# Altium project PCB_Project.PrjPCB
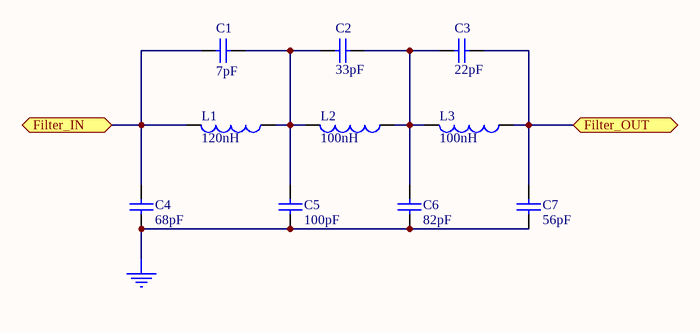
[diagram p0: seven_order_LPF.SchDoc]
4 sheets, 37 parts. Net scope: flat (ports and power ports of the same name join across sheets).
Sheets:
  Cable Modem.SchDoc
  seven_order_LPF.SchDoc
  AD9853.SchDoc
  AD8320.SchDoc

## Sheet Cable Modem.SchDoc
size B

## Sheet seven_order_LPF.SchDoc
size B

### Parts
(Parts that share a designator on the sheet are numbered #1, #2 ... from top to bottom, then left to right.)
C1#1  7pF  [C3216-1206]
C2#1  33pF  [C3216-1206]
C3#1  22pF  [C3216-1206]
C4#1  68pF  [C3216-1206]
C5#1  100pF  [C3216-1206]
C6#1  82pF  [C3216-1206]
C7#1  56pF  [C3216-1206]
L1  120nH  [C1005-0402]
L2  100nH  [C1005-0402]
L3  100nH  [C1005-0402]

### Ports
Filter_IN, Filter_OUT

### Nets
GND: C4#1.2 C5#1.2 C6#1.2 C7#1.2
NetC1#1_1: C1#1.1 C4#1.1 L1.2 ; port Filter_IN
NetC1#1_2: C1#1.2 C2#1.1 C5#1.1 L1.1 L2.2
NetC2#1_2: C2#1.2 C3#1.1 C6#1.1 L2.1 L3.2
NetC3#1_2: C3#1.2 C7#1.1 L3.1 ; port Filter_OUT

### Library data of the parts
C1#1 C2#1 C3#1 C4#1 C5#1 C6#1 C7#1 = Cap Semi: Capacitor (Semiconductor SIM Model); Manufacturer: Generic Components; Class I: Passive
L1-L3 = Inductor: Manufacturer: Generic Components; Class I: Passive

## Sheet AD9853.SchDoc
size B
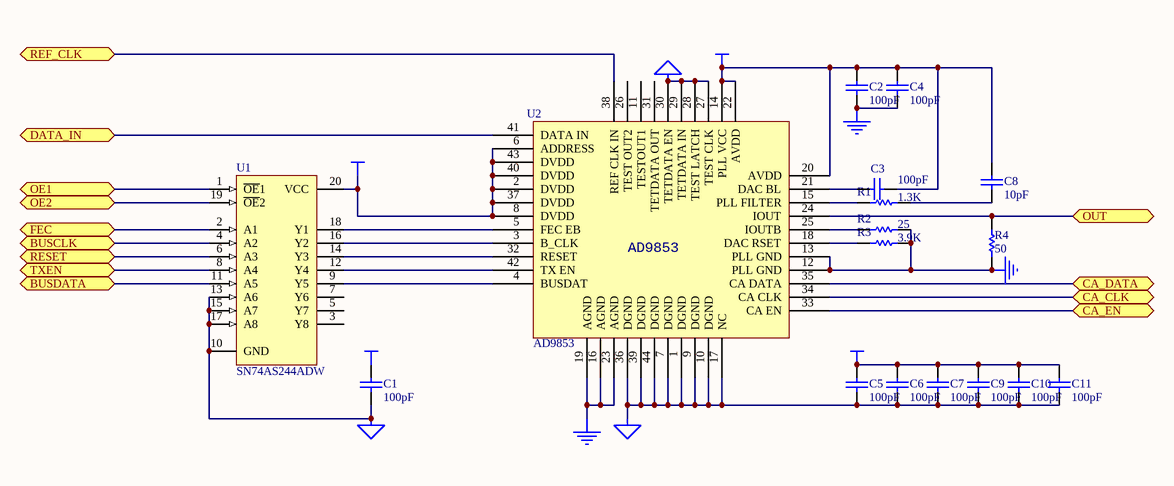
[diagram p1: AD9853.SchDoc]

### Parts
(Parts that share a designator on the sheet are numbered #1, #2 ... from top to bottom, then left to right.)
C1#2  100pF  [RAD-0.3]
C2#2  100pF  [RAD-0.3]
C3#2  100pF  [RAD-0.3]
C4#2  100pF  [RAD-0.3]
C5#2  100pF  [RAD-0.3]
C6#2  100pF  [RAD-0.3]
C7#2  100pF  [RAD-0.3]
C8#1  10pF  [RAD-0.3]
C9#1  100pF  [RAD-0.3]
C10  100pF  [RAD-0.3]
C11  100pF  [RAD-0.3]
R1  1.3K  [AXIAL-0.3]
R2  25  [AXIAL-0.3]
R3  3.9K  [AXIAL-0.3]
R4  50  [AXIAL-0.3]
U1#1  SN74AS244ADW  [SO-G20/G7.1]
U2  AD9853

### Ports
BUSCLK, BUSDATA, CA_CLK, CA_DATA, CA_EN, DATA_IN, FEC, OE1, OE2, OUT, REF_CLK, RESET, TXEN

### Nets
+5V: C2#2.2 C3#2.2 C4#2.2 C8#1.1 U2.14(PLL_VCC) U2.20(AVDD) U2.22(AVDD)
AGND: U2.16(AGND) U2.19(AGND) U2.23(AGND)
DUT +V: C1#2.2 C5#2.2 C6#2.2 C7#2.2 C9#1.2 C10.2 C11.2 U1#1.20(VCC) U2.2(DVDD) U2.6(ADDRESS) U2.8(DVDD) U2.37(DVDD) U2.40(DVDD) U2.43(DVDD)
GND: C2#2.1 C4#2.1 R2.2 R3.2 R4.1 U2.12(PLL_GND) U2.13(PLL_GND)
SGND: C1#2.1 C5#2.1 C6#2.1 C7#2.1 C9#1.1 C10.1 C11.1 U1#1.10(GND) U1#1.13(A6) U1#1.15(A7) U1#1.17(A8) U2.1(DGND) U2.7(DGND) U2.9(DGND) U2.10(DGND) U2.17(NC) U2.27(TEST_CLK) U2.28(TEST_LATCH) U2.29(TETDATA_IN) U2.30(TETDATA_EN) U2.36(DGND) U2.39(DGND) U2.44(DGND)
NetC3#2_1: C3#2.1 U2.21(DAC_BL)
NetC8#1_2: C8#1.2 R1.2
NetR1_1: R1.1 U2.15(PLL_FILTER)
NetR2_1: R2.1 U2.25(IOUTB)
NetR3_1: R3.1 U2.18(DAC_RSET)
NetR4_2: R4.2 U2.24(IOUT) ; port OUT
NetU1#1_1: U1#1.1(~{OE}1) ; port OE1
NetU1#1_2: U1#1.2(A1) ; port FEC
NetU1#1_4: U1#1.4(A2) ; port BUSCLK
NetU1#1_6: U1#1.6(A3) ; port RESET
NetU1#1_8: U1#1.8(A4) ; port TXEN
NetU1#1_9: U1#1.9(Y5) U2.4(BUSDAT)
NetU1#1_11: U1#1.11(A5) ; port BUSDATA
NetU1#1_12: U1#1.12(Y4) U2.42(TX_EN)
NetU1#1_14: U1#1.14(Y3) U2.32(RESET)
NetU1#1_16: U1#1.16(Y2) U2.3(B_CLK)
NetU1#1_18: U1#1.18(Y1) U2.5(FEC_EB)
NetU1#1_19: U1#1.19(~{OE}2) ; port OE2
NetU1#2_1: U2.35(CA_DATA) ; port CA_DATA
NetU1#2_2: U2.34(CA_CLK) ; port CA_CLK
NetU1#2_3: U2.33(CA_EN) ; port CA_EN
NetU2_38: U2.38(REF_CLK_IN) ; port REF_CLK
NetU2_41: U2.41(DATA_IN) ; port DATA_IN

Not connected (* = marked no-connect by the designer): U1#1 3(Y8) 5(Y7) 7(Y6); U2 11(TESTOUT1) 26(TEST_OUT2) 31(TETDATA_OUT)

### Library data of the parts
C1#2 C2#2 C3#2 C4#2 C5#2 C6#2 C7#2 C8#1 C9#1 C10 C11 = Cap: Capacitor; Manufacturer: Generic Components; Class I: Passive
R1-R4 = Res1: Resistor; Manufacturer: Generic Components; Class I: Passive
U1#1 = SN74AS244ADW: Octal Buffer/Driver with 3-State Outputs; Manufacturer: Texas Instruments; Package Information: Latest Revision: Dec-1998; Class I: Logic; Class II: Buffer/Line Driver
U2 = AD9853: Programmable Digital QPSK/16-QAM Modulator

## Sheet AD8320.SchDoc
size B
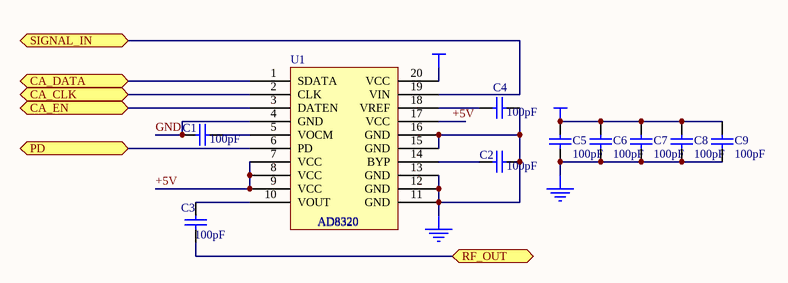
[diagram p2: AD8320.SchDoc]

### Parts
(Parts that share a designator on the sheet are numbered #1, #2 ... from top to bottom, then left to right.)
C1#3  100pF  [RAD-0.3]
C2#3  100pF  [RAD-0.3]
C3#3  100pF  [RAD-0.3]
C4#3  100pF  [RAD-0.3]
C5#3  100pF  [RAD-0.3]
C6#3  100pF  [RAD-0.3]
C7#3  100pF  [RAD-0.3]
C8#2  100pF  [RAD-0.3]
C9#2  100pF  [RAD-0.3]
U1#2  AD8320

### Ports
CA_CLK, CA_DATA, CA_EN, PD, RF_OUT, SIGNAL_IN

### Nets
+5V: C5#3.2 C6#3.2 C7#3.2 C8#2.2 C9#2.2 U1#2.7(VCC) U1#2.8(VCC) U1#2.9(VCC) U1#2.17(VCC) U1#2.20(VCC)
GND: C1#3.1 C2#3.2 C4#3.1 C5#3.1 C6#3.1 C7#3.1 C8#2.1 C9#2.1 U1#2.4(GND) U1#2.11(GND) U1#2.12(GND) U1#2.13(GND) U1#2.15(GND) U1#2.16(GND)
NetC1#3_2: C1#3.2 U1#2.5(VOCM)
NetC2#3_1: C2#3.1 U1#2.14(BYP)
NetC3#3_1: C3#3.1 ; port RF_OUT
NetC3#3_2: C3#3.2 U1#2.10(VOUT)
NetC4#3_2: C4#3.2 U1#2.18(VREF)
NetU1#2_1: U1#2.1(SDATA) ; port CA_DATA
NetU1#2_2: U1#2.2(CLK) ; port CA_CLK
NetU1#2_3: U1#2.3(DATEN) ; port CA_EN
NetU1#2_6: U1#2.6(PD) ; port PD
NetU1#2_19: U1#2.19(VIN) ; port SIGNAL_IN

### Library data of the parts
C1#3 C2#3 C3#3 C4#3 C5#3 C6#3 C7#3 C8#2 C9#2 = Cap: as C1#2 on sheet AD9853

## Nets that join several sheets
+5V: AD9853 (7 pins), AD8320 (10 pins)
GND: seven_order_LPF (C4#1.2 C5#1.2 C6#1.2 C7#1.2), AD9853 (7 pins), AD8320 (14 pins)
NetU1#2_1: AD9853 (U2.35), AD8320 (U1#2.1)
NetU1#2_2: AD9853 (U2.34), AD8320 (U1#2.2)
NetU1#2_3: AD9853 (U2.33), AD8320 (U1#2.3)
